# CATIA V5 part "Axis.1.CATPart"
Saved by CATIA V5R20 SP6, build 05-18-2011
Part number: Axis.1
Publications: "Center Point", "Line.1(Z Dir)", "Line.2(X Dir)", "Line.3(Y Dir)"
Bounding box of the stored display mesh (mm): x -20 to 20, y -20 to 20, z -20 to 20
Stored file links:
  C:\Work\#01 CATIA Lecture Materials\#299 TOYOTA CATIA V5\TOYOTA_CATIA\LCS\Solid\Solid EX03\Axis.1.CATPart
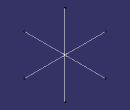
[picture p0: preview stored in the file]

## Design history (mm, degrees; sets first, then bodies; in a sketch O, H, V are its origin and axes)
Set1 "Axis"
  Point1 "Center Point": (0, 0, 0)
  Line1 "Line.1(Z Dir)": type PtDir, RefPoint Point1, Direction xy-plane, Start -20, End 20
  Line2 "Line.2(X Dir)": type PtDir, RefPoint Point1, Direction yz-plane, Start -20, End 20
  Line3 "Line.3(Y Dir)": type PtDir, RefPoint Point1, Direction zx-plane, Start -20, End 20
Body1 (main body)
